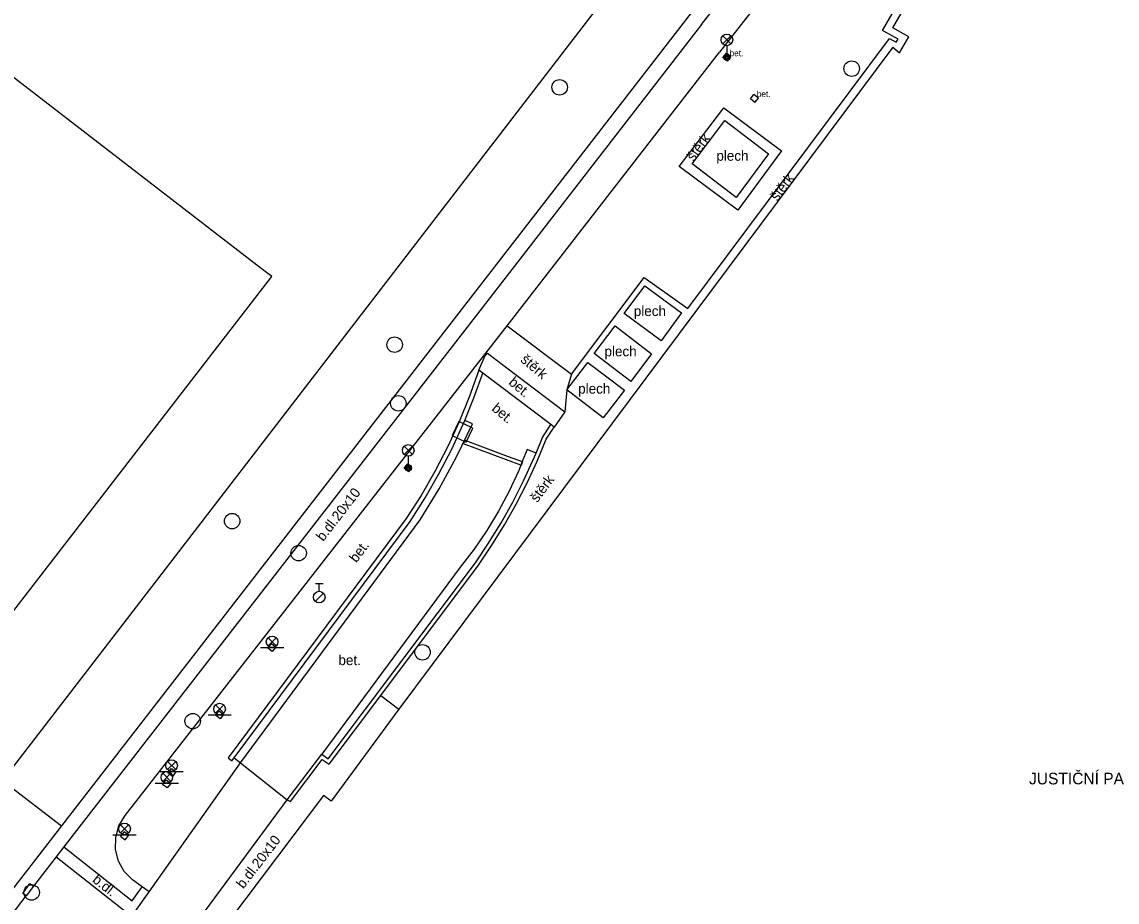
# Model space of a CAD drawing. Extents: x -598932 to -598196, y -1162207 to -1161504.
# Drawn here: x -598730.3 to -598659.5, y -1162101.4 to -1162044.5 of the extents above; entities that cross this region are included whole.
import ezdxf

# ---------------------------------------------------------------- set-up
doc = ezdxf.new("R2010")
doc.units = 0
for name, color, linetype in [('Level 26', 7, 'Continuous'), ('Level 27', 7, 'Continuous'), ('Level 28', 7, 'Continuous'), ('Level 33', 7, 'Continuous'), ('specificka linie pasportu komunikaci', 7, 'Continuous'), ('TM - budovy zdene_ betonove - VP', 7, 'Continuous'), ('TM - chodniky - VP', 7, 'Continuous'), ('TM - horni hrana svahu', 7, 'Continuous'), ('TM - komunikace - VP', 7, 'Continuous'), ('TM - letecke snimky - pomocna linie', 7, 'Continuous'), ('TM - plot dreveny_ kovovy - VP', 7, 'Continuous'), ('TM - popis objektu', 7, 'Continuous'), ('TM - popis povrchu', 7, 'Continuous'), ('TM - rozhrani mezi zpev. plochami mezi sebou - VP', 7, 'Continuous'), ('TM - rozhrani ploch obecne - VP', 7, 'Continuous'), ('TM - zed operna - VP', 7, 'Continuous')]:
    doc.layers.add(name, color=color, linetype=linetype)

msp = doc.modelspace()

# ---------------------------------------------------------------- linework, layer by layer
at = {"layer": 'Level 26'}
msp.add_lwpolyline([(-598701.575, -1162071.657), (-598701.143, -1162070.755), (-598702.045, -1162070.323), (-598702.477, -1162071.225)], close=True, dxfattribs=at)
at = {"layer": 'Level 27'}
for centre in [(-598676.68, -1162047.53), (-598695.54, -1162048.74), (-598706.19, -1162065.36), (-598705.95, -1162069.15), (-598716.68, -1162076.75), (-598712.39, -1162078.82), (-598704.39, -1162085.22), (-598719.23, -1162089.67), (-598729.63, -1162100.73)]:
    msp.add_circle(centre, 0.5, dxfattribs=at)
at = {"layer": 'Level 28'}
for p, q in [((-598711.31, -1162080.785), (-598710.81, -1162080.785)), ((-598711.06, -1162081.285), (-598711.06, -1162080.785)), ((-598711.318, -1162081.932), (-598710.788, -1162081.402))]:
    msp.add_line(p, q, dxfattribs=at)
msp.add_circle((-598711.06, -1162081.66), 0.375, dxfattribs=at)
at = {"layer": 'Level 33'}
for p, q in [((-598685.004, -1162045.94), (-598684.474, -1162045.41)), ((-598685.004, -1162045.41), (-598684.474, -1162045.94)), ((-598684.74, -1162046.05), (-598684.74, -1162046.8)), ((-598705.575, -1162072.45), (-598705.045, -1162071.92)), ((-598705.575, -1162071.92), (-598705.045, -1162072.45)), ((-598705.31, -1162072.56), (-598705.31, -1162073.31)), ((-598714.365, -1162084.81), (-598713.835, -1162084.28)), ((-598714.365, -1162084.28), (-598713.835, -1162084.81)), ((-598714.85, -1162084.92), (-598713.35, -1162084.92)), ((-598717.755, -1162089.15), (-598717.225, -1162088.62)), ((-598717.755, -1162088.62), (-598717.225, -1162089.15)), ((-598718.24, -1162089.26), (-598716.74, -1162089.26)), ((-598720.855, -1162092.8), (-598720.325, -1162092.27)), ((-598720.855, -1162092.27), (-598720.325, -1162092.8)), ((-598721.34, -1162092.91), (-598719.84, -1162092.91)), ((-598721.165, -1162093.56), (-598720.635, -1162093.03)), ((-598721.165, -1162093.03), (-598720.635, -1162093.56)), ((-598721.65, -1162093.67), (-598720.15, -1162093.67)), ((-598723.895, -1162096.89), (-598723.365, -1162096.36)), ((-598723.895, -1162096.36), (-598723.365, -1162096.89)), ((-598724.38, -1162097), (-598722.88, -1162097))]:
    msp.add_line(p, q, dxfattribs=at)
for centre, radius in [((-598684.739, -1162045.675), 0.375), ((-598684.74, -1162046.8), 0.2), ((-598684.74, -1162046.8), 0.145), ((-598684.74, -1162046.8), 0.0876), ((-598705.31, -1162072.185), 0.375), ((-598705.31, -1162073.31), 0.2), ((-598705.31, -1162073.31), 0.145), ((-598705.31, -1162073.31), 0.0876), ((-598714.1, -1162084.545), 0.375), ((-598717.49, -1162088.885), 0.375), ((-598720.59, -1162092.535), 0.375), ((-598720.9, -1162093.295), 0.375), ((-598723.63, -1162096.625), 0.375)]:
    msp.add_circle(centre, radius, dxfattribs=at)
at = {"layer": 'specificka linie pasportu komunikaci'}
for points in [[(-598694.78, -1162067.27), (-598695.07, -1162068.28)], [(-598695.07, -1162068.28), (-598695.2, -1162069.7)], [(-598716.56, -1162092.04), (-598716.14, -1162092.35)], [(-598729.98, -1162100.95), (-598730.193, -1162100.795), (-598729.742, -1162100.145), (-598729.5, -1162100.33)]]:
    msp.add_lwpolyline(points, dxfattribs=at)
at = {"layer": 'TM - budovy zdene_ betonove - VP'}
for points in [[(-598674.03, -1162046.14), (-598673.6, -1162046.51), (-598673, -1162045.47), (-598674.02, -1162044.89), (-598672.57, -1162042.36), (-598671.65, -1162040.74), (-598668.56, -1162035.34), (-598664.65, -1162037.57)], [(-598714.8, -1162060.44), (-598739.32, -1162041.51), (-598741.79, -1162039.6)], [(-598674.03, -1162046.14), (-598705.91, -1162088.89)], [(-598714.12, -1162060.96), (-598714.8, -1162060.44)], [(-598737, -1162090.55), (-598714.12, -1162060.96)], [(-598705.91, -1162088.89), (-598710.29, -1162094.83)], [(-598710.79, -1162094.46), (-598717.77, -1162103.75)], [(-598710.29, -1162094.83), (-598710.79, -1162094.46)]]:
    msp.add_lwpolyline(points, dxfattribs=at)
at = {"layer": 'TM - chodniky - VP'}
for points in [[(-598686.38, -1162044.69), (-598679.62, -1162036.02)], [(-598679.1, -1162038.63), (-598679.23, -1162038.81), (-598685.21, -1162046.47)], [(-598686.38, -1162044.69), (-598700.7, -1162063.17), (-598727.54, -1162097.79)], [(-598698.92, -1162064.14), (-598685.21, -1162046.47)], [(-598722.5, -1162100.36), (-598723.12, -1162099.92), (-598723.65, -1162099.38), (-598724.03, -1162098.7), (-598724.22, -1162097.95), (-598724.2, -1162097.18), (-598723.99, -1162096.43), (-598723.59, -1162095.77), (-598698.92, -1162064.14)], [(-598705.29, -1162073.57), (-598705.57, -1162073.34), (-598705.34, -1162073.05), (-598705.11, -1162073.31), (-598705.29, -1162073.57)], [(-598714.09, -1162085.18), (-598714.38, -1162084.95), (-598714.15, -1162084.66), (-598713.86, -1162084.89), (-598714.09, -1162085.18)], [(-598717.45, -1162089.52), (-598717.75, -1162089.29), (-598717.52, -1162089), (-598717.23, -1162089.23), (-598717.45, -1162089.52)], [(-598720.83, -1162093.01), (-598720.6, -1162092.72), (-598720.31, -1162092.95), (-598720.54, -1162093.24), (-598720.83, -1162093.01)], [(-598721.17, -1162093.75), (-598720.94, -1162093.46), (-598720.65, -1162093.69), (-598720.88, -1162093.98), (-598721.17, -1162093.75)], [(-598723.59, -1162097.33), (-598723.36, -1162097.04), (-598723.65, -1162096.81), (-598723.88, -1162097.1), (-598723.59, -1162097.33)], [(-598727.54, -1162097.79), (-598728.04, -1162098.44)], [(-598728.04, -1162098.44), (-598729.5, -1162100.33), (-598729.98, -1162100.95)], [(-598722.03, -1162100.68), (-598722.5, -1162100.36)], [(-598737.07, -1162110.22), (-598729.98, -1162100.95)]]:
    msp.add_lwpolyline(points, dxfattribs=at)
at = {"layer": 'TM - horni hrana svahu'}
for points in [[(-598698.04, -1162073.14), (-598701.75, -1162071.76), (-598701.66, -1162071.53)], [(-598701.66, -1162071.53), (-598700.51, -1162071.95), (-598698.87, -1162072.57), (-598697.95, -1162072.91)], [(-598697.95, -1162072.91), (-598697.94, -1162072.91), (-598698.03, -1162073.15), (-598698.04, -1162073.14)]]:
    msp.add_lwpolyline(points, dxfattribs=at)
at = {"layer": 'TM - komunikace - VP'}
for points in [[(-598701.66, -1162070.26), (-598701.07, -1162068.8), (-598700.5, -1162067.2)], [(-598716.94, -1162092.04), (-598716.7, -1162092.22), (-598716.56, -1162092.04), (-598705.19, -1162076.77), (-598704.23, -1162075.25), (-598703.33, -1162073.7), (-598702.5, -1162072.1), (-598701.66, -1162070.26)], [(-598716.14, -1162092.35), (-598704.54, -1162076.66), (-598703.31, -1162074.66), (-598702.19, -1162072.59), (-598701.17, -1162070.47), (-598701.66, -1162070.26)], [(-598697.06, -1162072.37), (-598696.65, -1162071.35), (-598696.1, -1162070.52)], [(-598710.89, -1162091.81), (-598710.49, -1162092.11), (-598700.98, -1162079.44), (-598700.12, -1162078.17), (-598699.31, -1162076.86), (-598698.56, -1162075.53), (-598697.87, -1162074.16), (-598697.06, -1162072.37)], [(-598713.12, -1162094.74), (-598710.89, -1162091.81)], [(-598722.03, -1162100.68), (-598716.14, -1162092.35)], [(-598719.14, -1162102.89), (-598713.12, -1162094.74)], [(-598723.74, -1162103.08), (-598722.03, -1162100.68)]]:
    msp.add_lwpolyline(points, dxfattribs=at)
at = {"layer": 'TM - letecke snimky - pomocna linie'}
msp.add_lwpolyline([(-598690.52, -1162040.21), (-598731.51, -1162093.49), (-598727.7, -1162096.43)], dxfattribs=at)
at = {"layer": 'TM - plot dreveny_ kovovy - VP'}
msp.add_lwpolyline([(-598687.05, -1162043.92), (-598727.7, -1162096.43), (-598737.84, -1162109.52), (-598781.4, -1162075.64), (-598785.64, -1162072.35)], dxfattribs=at)
at = {"layer": 'TM - rozhrani mezi zpev. plochami mezi sebou - VP'}
msp.add_lwpolyline([(-598728.04, -1162098.44), (-598723.6, -1162101.94), (-598724.19, -1162102.76)], dxfattribs=at)
at = {"layer": 'TM - rozhrani ploch obecne - VP'}
for points in [[(-598687.27, -1162063.03), (-598674.23, -1162045.58), (-598673.8, -1162045.83), (-598673.69, -1162045.64), (-598674.69, -1162045.07), (-598673, -1162042.12)], [(-598685, -1162046.82), (-598684.77, -1162046.53)], [(-598684.48, -1162046.77), (-598684.77, -1162046.53)], [(-598684.71, -1162047.06), (-598685, -1162046.82)], [(-598684.71, -1162047.06), (-598684.48, -1162046.77)], [(-598683.22, -1162049.49), (-598682.99, -1162049.2)], [(-598682.7, -1162049.43), (-598682.99, -1162049.2)], [(-598682.93, -1162049.72), (-598682.7, -1162049.43)], [(-598684.93, -1162050.06), (-598681.22, -1162052.83), (-598684.04, -1162056.67), (-598687.82, -1162053.85), (-598684.93, -1162050.06)], [(-598682.93, -1162049.72), (-598683.22, -1162049.49)], [(-598684.88, -1162050.88), (-598682.06, -1162053.03), (-598684.15, -1162055.85), (-598686.97, -1162053.69), (-598684.88, -1162050.88)], [(-598698.92, -1162064.14), (-598694.78, -1162067.27), (-598690.09, -1162061.01), (-598687.27, -1162063.03)], [(-598690.04, -1162061.55), (-598687.66, -1162063.31), (-598688.99, -1162065.11), (-598691.38, -1162063.35), (-598690.04, -1162061.55)], [(-598691.95, -1162064.14), (-598689.6, -1162065.94), (-598690.95, -1162067.73), (-598693.31, -1162065.93), (-598691.95, -1162064.14)], [(-598700.75, -1162067.01), (-598700.34, -1162066.06)], [(-598700.34, -1162066.06), (-598700.2, -1162065.9)], [(-598700.2, -1162065.9), (-598695.2, -1162069.7)], [(-598700.5, -1162067.2), (-598700.75, -1162067.01)], [(-598693.71, -1162066.5), (-598691.35, -1162068.29), (-598692.72, -1162070.08), (-598695.07, -1162068.28), (-598693.71, -1162066.5)], [(-598696.1, -1162070.52), (-598700.5, -1162067.2)], [(-598695.2, -1162069.7), (-598695.89, -1162070.68)], [(-598695.89, -1162070.68), (-598696.1, -1162070.52)], [(-598697.06, -1162072.37), (-598697.63, -1162072.13), (-598697.95, -1162072.91)], [(-598698.04, -1162073.14), (-598698.18, -1162073.48), (-598698.79, -1162074.81), (-598699.48, -1162076.1), (-598700.24, -1162077.35), (-598701.06, -1162078.56), (-598701.95, -1162079.72), (-598710.89, -1162091.81)], [(-598697.95, -1162072.91), (-598698.04, -1162073.14)], [(-598707.09, -1162088.01), (-598705.91, -1162088.89)], [(-598716.14, -1162092.35), (-598713.12, -1162094.74)], [(-598727.54, -1162097.79), (-598723.13, -1162101.27), (-598722.5, -1162100.36)]]:
    msp.add_lwpolyline(points, dxfattribs=at)
at = {"layer": 'TM - zed operna - VP'}
for points in [[(-598700.75, -1162067.01), (-598701.35, -1162068.69), (-598702.02, -1162070.34), (-598702.76, -1162071.94), (-598703.59, -1162073.55), (-598704.48, -1162075.09), (-598705.44, -1162076.59), (-598716.94, -1162092.04)], [(-598707.09, -1162088.01), (-598700.77, -1162079.59), (-598699.91, -1162078.31), (-598699.09, -1162077), (-598698.34, -1162075.65), (-598697.64, -1162074.28), (-598696.99, -1162072.88), (-598696.4, -1162071.45), (-598695.89, -1162070.68)], [(-598713.12, -1162094.74), (-598712.91, -1162094.86), (-598710.87, -1162092.14), (-598710.42, -1162092.45), (-598707.09, -1162088.01)]]:
    msp.add_lwpolyline(points, dxfattribs=at)

# ---------------------------------------------------------------- texts
at = {"layer": 'TM - popis objektu'}
msp.add_text('JUSTIČNÍ PALÁC', height=0.75, dxfattribs=at).set_placement((-598665.23, -1162093.75))
at = {"layer": 'TM - popis povrchu'}
for s, height, rotation, p in [('bet.', 0.4, 359.96271, (-598684.57, -1162046.73)), ('bet.', 0.4, 359.96271, (-598682.81, -1162049.37)), ('štěrk', 0.65, 53.36, (-598686.89, -1162053.56)), ('štěrk', 0.65, 53, (-598681.48, -1162056.13)), ('štěrk', 0.65, 319.8, (-598698.11, -1162066.41)), ('bet.', 0.65, 319.8, (-598698.88, -1162067.87)), ('bet.', 0.65, 319.8, (-598699.97, -1162069.56)), ('štěrk', 0.65, 53.18, (-598696.98, -1162075.59)), ('b.dl.20x10', 0.65, 52.37, (-598710.8, -1162078.1)), ('bet.', 0.65, 53.34, (-598708.66, -1162079.48)), ('b.dl.20x10', 0.65, 52.37, (-598715.96, -1162100.53)), ('b.dl.', 0.65, 321.75, (-598725.76, -1162100.01))]:
    msp.add_text(s, height=height, rotation=rotation, dxfattribs=at).set_placement(p)
for s, p in [('plech', (-598685.42, -1162053.48)), ('plech', (-598690.75, -1162063.51)), ('plech', (-598692.64, -1162066.11)), ('plech', (-598694.34, -1162068.52)), ('bet.', (-598709.82, -1162086.05))]:
    msp.add_text(s, height=0.65, dxfattribs=at).set_placement(p)

doc.saveas('drawing.dxf')
